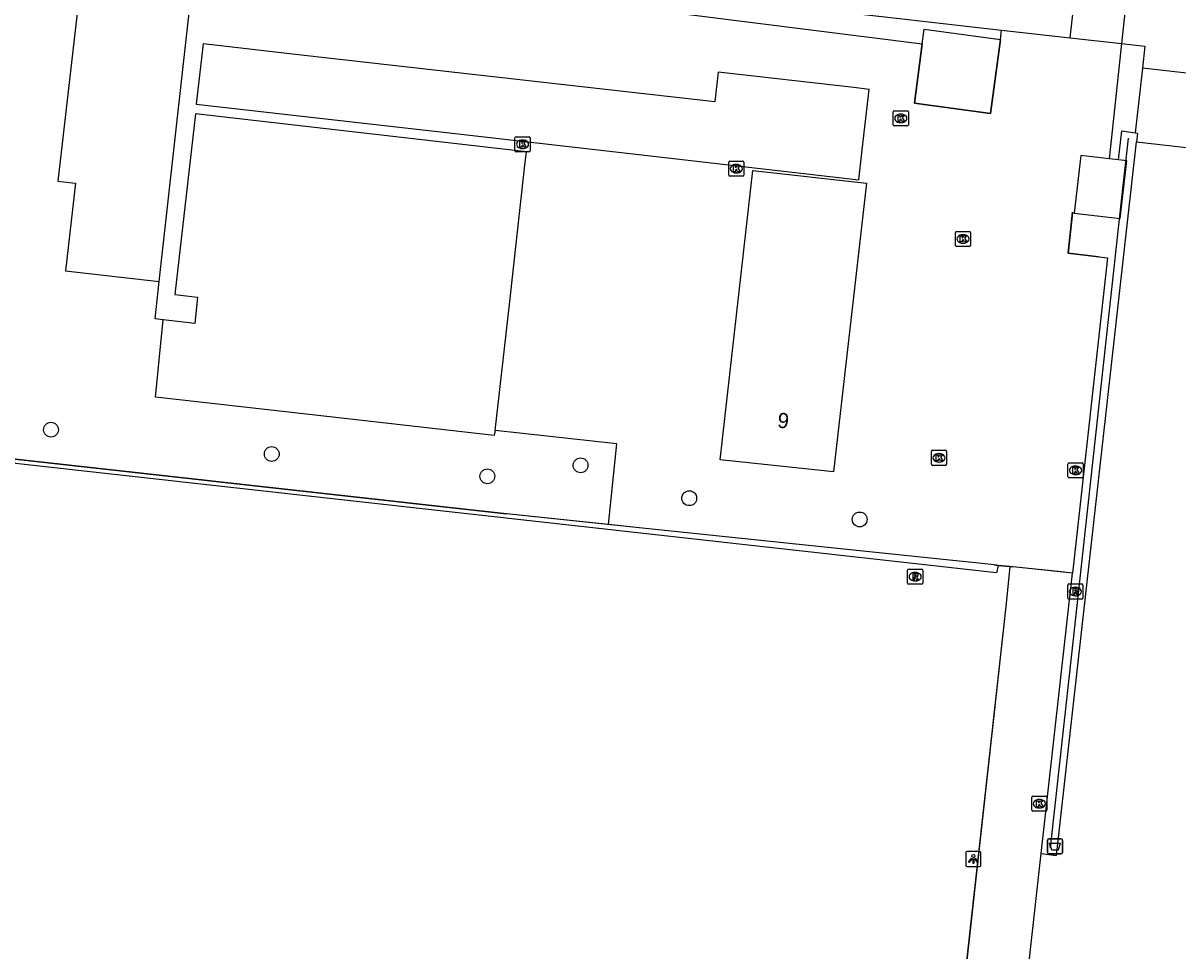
# Model space of a CAD drawing. Extents: x 162515 to 163909, y 388494 to 389773.
# Drawn here: x 162940.6 to 163016.8, y 388781.6 to 388842.8 of the extents above; entities that cross this region are included whole.
import ezdxf

# ---------------------------------------------------------------- set-up
doc = ezdxf.new("R2010")
doc.units = 0
for name, color, linetype in [('IMGEO_Afvalbak', 7, 'Continuous'), ('IMGEO_Boom', 7, 'Continuous'), ('IMGEO_Groenvoorziening', 7, 'Continuous'), ('IMGEO_Hek', 7, 'Continuous'), ('IMGEO_Houtwal', 7, 'Continuous'), ('IMGEO_Kolk', 7, 'Continuous'), ('IMGEO_Lichtpunt', 7, 'Continuous'), ('IMGEO_Loofbos', 7, 'Continuous'), ('IMGEO_Pand', 7, 'Continuous'), ('IMGEO_Pand_nummerreeks', 7, 'Continuous'), ('IMGEO_Rijbaan_lokaal_open', 7, 'Continuous'), ('IMGEO_Rioolput', 7, 'Continuous'), ('IMGEO_Voetpad_onverhard', 7, 'Continuous'), ('IMGEO_Voetpad_open', 7, 'Continuous')]:
    doc.layers.add(name, color=color, linetype=linetype)

msp = doc.modelspace()

# ---------------------------------------------------------------- linework, layer by layer
at = {"layer": 'IMGEO_Afvalbak'}
for p, q in [((163008.161, 388788.14), (163008.161, 388788.94)), ((163008.161, 388788.94), (163008.161, 388788.14)), ((163008.261, 388789.04), (163009.051, 388789.04)), ((163009.051, 388789.04), (163008.261, 388789.04)), ((163009.151, 388788.94), (163009.151, 388788.14)), ((163009.151, 388788.14), (163009.151, 388788.94)), ((163009.051, 388788.04), (163008.261, 388788.04)), ((163008.261, 388788.04), (163009.051, 388788.04))]:
    msp.add_line(p, q, dxfattribs=at)
msp.add_lwpolyline([(163008.304, 388788.754), (163009.008, 388788.754), (163008.859, 388788.284), (163008.453, 388788.284), (163008.304, 388788.754)], dxfattribs=at)
for centre, start, end in [((163008.261, 388788.94), 90, 180), ((163008.261, 388788.94), 90, 180), ((163009.051, 388788.94), 0, 90), ((163009.051, 388788.94), 360, 90), ((163008.261, 388788.14), 180, 270), ((163008.261, 388788.14), 180, 270), ((163009.051, 388788.14), 270, 0), ((163009.051, 388788.14), 270, 0)]:
    msp.add_arc(centre, 0.1, start, end, dxfattribs=at)
at = {"layer": 'IMGEO_Boom'}
for centre in [(162942.422, 388816.014), (162956.989, 388814.409), (162977.362, 388813.669), (162971.209, 388812.942), (162984.528, 388811.498), (162995.773, 388810.096)]:
    msp.add_circle(centre, 0.489, dxfattribs=at)
at = {"layer": 'IMGEO_Groenvoorziening'}
for points in [[(163004.9, 388807.069), (163004.798, 388806.577), (162867.846, 388821.822), (162872.238, 388860.105), (162871.559, 388861.161), (162799.041, 388869.269)], [(162979.197, 388809.763), (162972.476, 388810.468), (162868.327, 388822.062), (162872.602, 388861.371)], [(162999.905, 388841.465), (163000.034, 388842.427), (163005.06, 388841.755)]]:
    msp.add_lwpolyline(points, dxfattribs=at)
at = {"layer": 'IMGEO_Hek'}
for points in [[(162872.602, 388861.371), (162868.327, 388822.062), (162972.476, 388810.468)], [(162997.437, 388843.236), (163005.122, 388842.376), (163009.67, 388841.867)], [(162999.381, 388837.545), (162999.905, 388841.465), (163000.034, 388842.427)], [(163000.034, 388842.427), (163005.06, 388841.755)], [(163005.06, 388841.755), (163004.407, 388836.873)], [(163009.67, 388841.867), (163013.046, 388841.484)], [(163013.046, 388841.484), (163014.583, 388841.309), (163014.422, 388839.85)], [(163014.422, 388839.85), (163013.951, 388835.598)], [(163004.407, 388836.873), (162999.381, 388837.545)], [(163008.368, 388788.444), (163009.813, 388801.599), (163013.076, 388831.3), (163013.51, 388835.244)], [(163014.044, 388835.011), (163119.889, 388822.986), (163111.679, 388750)], [(163011.529, 388827.418), (163009.522, 388827.661), (163009.819, 388830.371)], [(162981.636, 388809.507), (162972.476, 388810.468)], [(163003.824, 388807.181), (163000, 388807.582), (162981.636, 388809.507)], [(163004.637, 388807.096), (163003.824, 388807.181)], [(163004.637, 388807.096), (163004.9, 388807.069)], [(163005.689, 388806.988), (163005.427, 388804.551), (162995.492, 388714.399)], [(163004.9, 388807.069), (163005.689, 388806.988), (163005.868, 388806.969)], [(163009.285, 388806.615), (163005.868, 388806.969)]]:
    msp.add_lwpolyline(points, dxfattribs=at)
at = {"layer": 'IMGEO_Houtwal'}
msp.add_lwpolyline([(162872.602, 388861.371), (162879.687, 388860.474), (162888.818, 388859.069), (162976.404, 388845.59), (162997.437, 388843.236), (163005.122, 388842.376)], dxfattribs=at)
at = {"layer": 'IMGEO_Kolk'}
for p, q in [((162997.987, 388836.122), (162997.987, 388836.974)), ((162998.062, 388837.048), (162998.914, 388837.048)), ((162998.475, 388836.828), (162998.5, 388836.828)), ((162998.988, 388836.974), (162998.988, 388836.122)), ((162998.914, 388836.048), (162998.062, 388836.048)), ((162998.498, 388836.268), (162998.473, 388836.268)), ((162973.109, 388835.341), (162973.961, 388835.341)), ((162973.034, 388834.415), (162973.034, 388835.267)), ((162973.545, 388834.561), (162973.52, 388834.561)), ((162973.522, 388835.121), (162973.547, 388835.121)), ((162974.035, 388835.267), (162974.035, 388834.415)), ((162973.961, 388834.341), (162973.109, 388834.341)), ((162987.135, 388832.805), (162987.135, 388833.657)), ((162987.21, 388833.731), (162988.062, 388833.731)), ((162987.623, 388833.511), (162987.648, 388833.511)), ((162988.136, 388833.657), (162988.136, 388832.805)), ((162988.062, 388832.731), (162987.21, 388832.731)), ((162987.646, 388832.951), (162987.621, 388832.951)), ((163002.092, 388828.171), (163002.092, 388829.023)), ((163002.167, 388829.097), (163003.019, 388829.097)), ((163002.58, 388828.877), (163002.605, 388828.877)), ((163003.093, 388829.023), (163003.093, 388828.171)), ((163003.019, 388828.097), (163002.167, 388828.097)), ((163002.603, 388828.317), (163002.578, 388828.317)), ((163000.505, 388813.732), (163000.505, 388814.584)), ((163000.58, 388814.658), (163001.432, 388814.658)), ((163000.993, 388814.438), (163001.018, 388814.438)), ((163001.506, 388814.584), (163001.506, 388813.732)), ((163001.432, 388813.658), (163000.58, 388813.658)), ((163001.016, 388813.878), (163000.991, 388813.878)), ((163009.516, 388812.91), (163009.516, 388813.762)), ((163009.591, 388813.836), (163010.443, 388813.836)), ((163010.004, 388813.616), (163010.029, 388813.616)), ((163010.517, 388813.762), (163010.517, 388812.91)), ((163010.443, 388812.836), (163009.591, 388812.836)), ((163010.027, 388813.056), (163010.002, 388813.056)), ((163007.128, 388790.922), (163007.128, 388791.774)), ((163007.203, 388791.848), (163008.055, 388791.848)), ((163007.616, 388791.628), (163007.641, 388791.628)), ((163008.129, 388791.774), (163008.129, 388790.922)), ((163008.055, 388790.848), (163007.203, 388790.848)), ((163007.639, 388791.068), (163007.614, 388791.068))]:
    msp.add_line(p, q, dxfattribs=at)
for points in [[(162997.987, 388836.122), (162997.987, 388836.974)], [(162998.062, 388837.048), (162998.914, 388837.048)], [(162998.988, 388836.974), (162998.988, 388836.122)], [(162998.914, 388836.048), (162998.062, 388836.048)], [(162998.308, 388836.748), (162998.431, 388836.748), (162998.431, 388836.597), (162998.561, 388836.748), (162998.725, 388836.748), (162998.579, 388836.597), (162998.732, 388836.348), (162998.58, 388836.348), (162998.495, 388836.512), (162998.431, 388836.445), (162998.431, 388836.348), (162998.308, 388836.348), (162998.308, 388836.748)], [(162973.109, 388835.341), (162973.961, 388835.341)], [(162973.034, 388834.415), (162973.034, 388835.267)], [(162973.355, 388835.041), (162973.478, 388835.041), (162973.478, 388834.89), (162973.608, 388835.041), (162973.772, 388835.041), (162973.626, 388834.89), (162973.779, 388834.641), (162973.627, 388834.641), (162973.542, 388834.805), (162973.478, 388834.738), (162973.478, 388834.641), (162973.355, 388834.641), (162973.355, 388835.041)], [(162974.035, 388835.267), (162974.035, 388834.415)], [(162973.961, 388834.341), (162973.109, 388834.341)], [(162987.135, 388832.805), (162987.135, 388833.657)], [(162987.21, 388833.731), (162988.062, 388833.731)], [(162987.456, 388833.431), (162987.579, 388833.431), (162987.579, 388833.28), (162987.709, 388833.431), (162987.873, 388833.431), (162987.727, 388833.28), (162987.88, 388833.031), (162987.728, 388833.031), (162987.643, 388833.195), (162987.579, 388833.128), (162987.579, 388833.031), (162987.456, 388833.031), (162987.456, 388833.431)], [(162988.136, 388833.657), (162988.136, 388832.805)], [(162988.062, 388832.731), (162987.21, 388832.731)], [(163002.092, 388828.171), (163002.092, 388829.023)], [(163002.167, 388829.097), (163003.019, 388829.097)], [(163002.413, 388828.797), (163002.536, 388828.797), (163002.536, 388828.646), (163002.666, 388828.797), (163002.83, 388828.797), (163002.684, 388828.646), (163002.837, 388828.397), (163002.685, 388828.397), (163002.6, 388828.561), (163002.536, 388828.494), (163002.536, 388828.397), (163002.413, 388828.397), (163002.413, 388828.797)], [(163003.093, 388829.023), (163003.093, 388828.171)], [(163003.019, 388828.097), (163002.167, 388828.097)], [(163000.505, 388813.732), (163000.505, 388814.584)], [(163000.58, 388814.658), (163001.432, 388814.658)], [(163000.826, 388814.358), (163000.949, 388814.358), (163000.949, 388814.207), (163001.079, 388814.358), (163001.243, 388814.358), (163001.097, 388814.207), (163001.25, 388813.958), (163001.098, 388813.958), (163001.013, 388814.122), (163000.949, 388814.055), (163000.949, 388813.958), (163000.826, 388813.958), (163000.826, 388814.358)], [(163001.506, 388814.584), (163001.506, 388813.732)], [(163001.432, 388813.658), (163000.58, 388813.658)], [(163009.516, 388812.91), (163009.516, 388813.762)], [(163009.591, 388813.836), (163010.443, 388813.836)], [(163009.837, 388813.536), (163009.96, 388813.536), (163009.96, 388813.385), (163010.09, 388813.536), (163010.254, 388813.536), (163010.108, 388813.385), (163010.261, 388813.136), (163010.109, 388813.136), (163010.024, 388813.3), (163009.96, 388813.233), (163009.96, 388813.136), (163009.837, 388813.136), (163009.837, 388813.536)], [(163010.517, 388813.762), (163010.517, 388812.91)], [(163010.443, 388812.836), (163009.591, 388812.836)], [(163007.128, 388790.922), (163007.128, 388791.774)], [(163007.203, 388791.848), (163008.055, 388791.848)], [(163007.449, 388791.548), (163007.572, 388791.548), (163007.572, 388791.397), (163007.702, 388791.548), (163007.866, 388791.548), (163007.72, 388791.397), (163007.873, 388791.148), (163007.721, 388791.148), (163007.636, 388791.312), (163007.572, 388791.245), (163007.572, 388791.148), (163007.449, 388791.148), (163007.449, 388791.548)], [(163008.129, 388791.774), (163008.129, 388790.922)], [(163008.055, 388790.848), (163007.203, 388790.848)]]:
    msp.add_lwpolyline(points, dxfattribs=at)
for centre, start, end in [((162998.064, 388836.972), 91.55205, 178.44795), ((162998.064, 388836.972), 91.55205, 178.44795), ((162998.912, 388836.972), 1.55205, 88.44795), ((162998.912, 388836.972), 1.55205, 88.44795), ((162998.064, 388836.124), 181.55205, 268.44795), ((162998.064, 388836.124), 181.55205, 268.44795), ((162998.912, 388836.124), 271.55205, 358.44795), ((162998.912, 388836.124), 271.55205, 358.44795), ((162973.111, 388835.265), 91.55205, 178.44795), ((162973.111, 388835.265), 91.55205, 178.44795), ((162973.959, 388835.265), 1.55205, 88.44795), ((162973.959, 388835.265), 1.55205, 88.44795), ((162973.111, 388834.417), 181.55205, 268.44795), ((162973.111, 388834.417), 181.55205, 268.44795), ((162973.959, 388834.417), 271.55205, 358.44795), ((162973.959, 388834.417), 271.55205, 358.44795), ((162987.212, 388833.655), 91.55205, 178.44795), ((162987.212, 388833.655), 91.55205, 178.44795), ((162988.06, 388833.655), 1.55205, 88.44795), ((162988.06, 388833.655), 1.55205, 88.44795), ((162987.212, 388832.807), 181.55205, 268.44795), ((162987.212, 388832.807), 181.55205, 268.44795), ((162988.06, 388832.807), 271.55205, 358.44795), ((162988.06, 388832.807), 271.55205, 358.44795), ((163002.169, 388829.021), 91.55205, 178.44795), ((163002.169, 388829.021), 91.55205, 178.44795), ((163003.017, 388829.021), 1.55205, 88.44795), ((163003.017, 388829.021), 1.55205, 88.44795), ((163002.169, 388828.173), 181.55205, 268.44795), ((163002.169, 388828.173), 181.55205, 268.44795), ((163003.017, 388828.173), 271.55205, 358.44795), ((163003.017, 388828.173), 271.55205, 358.44795), ((163000.582, 388814.582), 91.55205, 178.44795), ((163000.582, 388814.582), 91.55205, 178.44795), ((163001.43, 388814.582), 1.55205, 88.44795), ((163001.43, 388814.582), 1.55205, 88.44795), ((163000.582, 388813.734), 181.55205, 268.44795), ((163000.582, 388813.734), 181.55205, 268.44795), ((163001.43, 388813.734), 271.55205, 358.44795), ((163001.43, 388813.734), 271.55205, 358.44795), ((163009.593, 388813.76), 91.55205, 178.44795), ((163009.593, 388813.76), 91.55205, 178.44795), ((163010.441, 388813.76), 1.55205, 88.44795), ((163010.441, 388813.76), 1.55205, 88.44795), ((163009.593, 388812.912), 181.55205, 268.44795), ((163009.593, 388812.912), 181.55205, 268.44795), ((163010.441, 388812.912), 271.55205, 358.44795), ((163010.441, 388812.912), 271.55205, 358.44795), ((163007.205, 388791.772), 91.55205, 178.44795), ((163007.205, 388791.772), 91.55205, 178.44795), ((163008.053, 388791.772), 1.55205, 88.44795), ((163008.053, 388791.772), 1.55205, 88.44795), ((163007.205, 388790.924), 181.55205, 268.44795), ((163007.205, 388790.924), 181.55205, 268.44795), ((163008.053, 388790.924), 271.55205, 358.44795), ((163008.053, 388790.924), 271.55205, 358.44795)]:
    msp.add_arc(centre, 0.0765, start, end, dxfattribs=at)
for centre, major_axis, ratio, start_param, end_param in [((162998.474, 388836.548), (-0.387, 0.002), 0.722429, 4.712389, 7.853982), ((162998.499, 388836.548), (-0.39, 0.002), 0.717154, 1.570796, 4.712389), ((162973.521, 388834.841), (-0.387, 0.002), 0.722429, 4.712389, 7.853982), ((162973.546, 388834.841), (-0.39, 0.002), 0.717154, 1.570796, 4.712389), ((162987.622, 388833.231), (-0.387, 0.002), 0.722429, 4.712389, 7.853982), ((162987.647, 388833.231), (-0.39, 0.002), 0.717154, 1.570796, 4.712389), ((163002.579, 388828.597), (-0.387, 0.002), 0.722429, 4.712389, 7.853982), ((163002.604, 388828.597), (-0.39, 0.002), 0.717154, 1.570796, 4.712389), ((163000.992, 388814.158), (-0.387, 0.002), 0.722429, 4.712389, 7.853982), ((163001.017, 388814.158), (-0.39, 0.002), 0.717154, 1.570796, 4.712389), ((163010.003, 388813.336), (-0.387, 0.002), 0.722429, 4.712389, 7.853982), ((163010.028, 388813.336), (-0.39, 0.002), 0.717154, 1.570796, 4.712389), ((163007.615, 388791.348), (-0.387, 0.002), 0.722429, 4.712389, 7.853982), ((163007.64, 388791.348), (-0.39, 0.002), 0.717154, 1.570796, 4.712389)]:
    msp.add_ellipse(centre, major_axis=major_axis, ratio=ratio, start_param=start_param, end_param=end_param, dxfattribs=at)
at = {"layer": 'IMGEO_Lichtpunt'}
for p, q in [((163002.775, 388788.101), (163002.775, 388787.294)), ((163002.775, 388788.101), (163002.775, 388787.294)), ((163003.677, 388788.196), (163002.869, 388788.196)), ((163003.677, 388788.196), (163002.869, 388788.196)), ((163003.771, 388787.294), (163003.771, 388788.101)), ((163003.771, 388787.294), (163003.771, 388788.101)), ((163002.869, 388787.2), (163003.677, 388787.2)), ((163002.869, 388787.2), (163003.677, 388787.2))]:
    msp.add_line(p, q, dxfattribs=at)
for points in [[(163003.149, 388787.765), (163003.188, 388787.737), (163003, 388787.475), (163002.962, 388787.502), (163003.149, 388787.765)], [(163003.251, 388787.717), (163003.298, 388787.717), (163003.298, 388787.395), (163003.251, 388787.395), (163003.251, 388787.717)], [(163003.361, 388787.737), (163003.399, 388787.764), (163003.586, 388787.502), (163003.547, 388787.474), (163003.361, 388787.737)]]:
    msp.add_lwpolyline(points, dxfattribs=at)
msp.add_circle((163003.274, 388787.899), 0.0994, dxfattribs=at)
for centre, start, end in [((163002.869, 388788.101), 90, 180), ((163002.869, 388788.101), 90, 180), ((163003.677, 388788.101), 0, 90), ((163003.677, 388788.101), 0, 90), ((163002.869, 388787.294), 180, 270), ((163002.869, 388787.294), 180, 270), ((163003.677, 388787.294), 270, 0), ((163003.677, 388787.294), 270, 360)]:
    msp.add_arc(centre, 0.0946, start, end, dxfattribs=at)
at = {"layer": 'IMGEO_Loofbos'}
msp.add_lwpolyline([(163014.044, 388835.011), (163119.889, 388822.986), (163111.679, 388750), (163104.95, 388690.968)], dxfattribs=at)
at = {"layer": 'IMGEO_Pand'}
for points in [[(163012.226, 388833.889), (163010.366, 388834.104), (163009.927, 388830.299)], [(163009.927, 388830.299), (163012.968, 388829.949), (163013.407, 388833.753), (163012.85, 388833.817)], [(163012.85, 388833.817), (163012.226, 388833.889)], [(162988.731, 388833.119), (162996.215, 388832.282), (162994.057, 388813.226), (162986.579, 388814.028), (162988.731, 388833.119)]]:
    msp.add_lwpolyline(points, dxfattribs=at)
at = {"layer": 'IMGEO_Rijbaan_lokaal_open'}
for points in [[(163013.705, 388847.595), (163013.046, 388841.484)], [(163009.67, 388841.867), (163009.923, 388844.191)], [(163009.67, 388841.867), (163013.046, 388841.484)]]:
    msp.add_lwpolyline(points, dxfattribs=at)
at = {"layer": 'IMGEO_Rioolput'}
for p, q in [((162998.933, 388805.896), (162998.933, 388806.748)), ((162999.008, 388806.822), (162999.86, 388806.822)), ((162999.421, 388806.602), (162999.446, 388806.602)), ((162999.934, 388806.748), (162999.934, 388805.896)), ((162999.86, 388805.822), (162999.008, 388805.822)), ((162999.444, 388806.042), (162999.419, 388806.042)), ((163009.499, 388804.914), (163009.499, 388805.766)), ((163009.574, 388805.84), (163010.426, 388805.84)), ((163009.987, 388805.62), (163010.012, 388805.62)), ((163010.5, 388805.766), (163010.5, 388804.914)), ((163010.426, 388804.84), (163009.574, 388804.84)), ((163010.01, 388805.06), (163009.985, 388805.06))]:
    msp.add_line(p, q, dxfattribs=at)
for points in [[(162998.933, 388805.896), (162998.933, 388806.748)], [(162999.008, 388806.822), (162999.86, 388806.822)], [(162999.522, 388806.52), (162999.27, 388806.522), (162999.27, 388806.122)], [(162999.448, 388806.441), (162999.394, 388806.441), (162999.394, 388806.36)], [(162999.394, 388806.36), (162999.446, 388806.36)], [(162999.934, 388806.748), (162999.934, 388805.896)], [(162999.86, 388805.822), (162999.008, 388805.822)], [(162999.27, 388806.122), (162999.394, 388806.122), (162999.394, 388806.284), (162999.405, 388806.284)], [(162999.452, 388806.255), (162999.523, 388806.122), (162999.663, 388806.122), (162999.598, 388806.248)], [(163009.499, 388804.914), (163009.499, 388805.766)], [(163009.574, 388805.84), (163010.426, 388805.84)], [(163010.5, 388805.766), (163010.5, 388804.914)], [(163010.426, 388804.84), (163009.574, 388804.84)], [(163010.088, 388805.538), (163009.836, 388805.54), (163009.836, 388805.14)], [(163009.836, 388805.14), (163009.96, 388805.14), (163009.96, 388805.302), (163009.971, 388805.302)], [(163010.014, 388805.459), (163009.96, 388805.459), (163009.96, 388805.378)], [(163009.96, 388805.378), (163010.012, 388805.378)], [(163010.018, 388805.273), (163010.089, 388805.14), (163010.229, 388805.14), (163010.164, 388805.266)]]:
    msp.add_lwpolyline(points, dxfattribs=at)
for centre, radius, start, end in [((162999.01, 388806.746), 0.0765, 91.55205, 178.44795), ((162999.01, 388806.746), 0.0765, 91.55205, 178.44795), ((162999.43, 388806.549), 0.19, 274.7715, 282.96867), ((162999.454, 388806.345), 0.0964, 77.00612, 93.18647), ((162999.468, 388806.402), 0.0378, 276.66336, 79.67722), ((162999.521, 388806.41), 0.109, 350.36119, 89.41601), ((162999.519, 388806.41), 0.112, 277.58423, 350.98172), ((162999.858, 388806.746), 0.0765, 1.55205, 88.44795), ((162999.858, 388806.746), 0.0765, 1.55205, 88.44795), ((162999.01, 388805.898), 0.0765, 181.55205, 268.44795), ((162999.01, 388805.898), 0.0765, 181.55205, 268.44795), ((162999.404, 388806.231), 0.0533, 26.02933, 88.69889), ((162999.503, 388806.195), 0.108, 29.51342, 73.79051), ((162999.858, 388805.898), 0.0765, 271.55205, 358.44795), ((162999.858, 388805.898), 0.0765, 271.55205, 358.44795), ((163009.576, 388805.764), 0.0765, 91.55205, 178.44795), ((163009.576, 388805.764), 0.0765, 91.55205, 178.44795), ((163010.424, 388805.764), 0.0765, 1.55205, 88.44795), ((163010.424, 388805.764), 0.0765, 1.55205, 88.44795), ((163009.576, 388804.916), 0.0765, 181.55205, 268.44795), ((163009.576, 388804.916), 0.0765, 181.55205, 268.44795), ((163009.97, 388805.249), 0.0533, 26.02933, 88.69889), ((163009.996, 388805.567), 0.19, 274.7715, 282.96867), ((163010.02, 388805.363), 0.0964, 77.00612, 93.18647), ((163010.034, 388805.42), 0.0378, 276.66336, 79.67722), ((163010.087, 388805.428), 0.109, 350.36119, 89.41601), ((163010.085, 388805.428), 0.112, 277.58423, 350.98172), ((163010.069, 388805.213), 0.108, 29.51342, 73.79051), ((163010.424, 388804.916), 0.0765, 271.55205, 358.44795), ((163010.424, 388804.916), 0.0765, 271.55205, 358.44795)]:
    msp.add_arc(centre, radius, start, end, dxfattribs=at)
for centre, major_axis, ratio, start_param, end_param in [((162999.42, 388806.322), (-0.387, 0.002), 0.722429, 4.712389, 7.853982), ((162999.445, 388806.322), (-0.39, 0.002), 0.717154, 1.570796, 4.712389), ((163009.986, 388805.34), (-0.387, 0.002), 0.722429, 4.712389, 7.853982), ((163010.011, 388805.34), (-0.39, 0.002), 0.717154, 1.570796, 4.712389)]:
    msp.add_ellipse(centre, major_axis=major_axis, ratio=ratio, start_param=start_param, end_param=end_param, dxfattribs=at)
at = {"layer": 'IMGEO_Voetpad_onverhard'}
msp.add_lwpolyline([(163126.231, 388787.847), (163125.858, 388790.634), (163123.55, 388799.176), (163125.824, 388819.514), (163124.377, 388827.421), (163014.422, 388839.85)], dxfattribs=at)
at = {"layer": 'IMGEO_Voetpad_open'}
for points in [[(162951.853, 388846.32), (162951.985, 388847.505), (162999.905, 388841.465)], [(162951.853, 388846.32), (162944.568, 388847.133), (162942.876, 388832.417), (162944.053, 388832.282), (162943.388, 388826.504), (162949.563, 388825.794)], [(162949.563, 388825.794), (162951.652, 388844.52), (162951.853, 388846.32)], [(163005.06, 388841.755), (163005.122, 388842.376)], [(163005.122, 388842.376), (163009.67, 388841.867)], [(162995.94, 388834.483), (162996.391, 388838.463), (162995.379, 388838.578), (162986.443, 388839.59), (162986.214, 388837.63), (162959.136, 388840.698), (162952.454, 388841.455), (162952.006, 388837.489), (162969.276, 388835.519), (162981.195, 388834.159), (162995.716, 388832.502), (162995.94, 388834.483)], [(162999.905, 388841.465), (162999.381, 388837.545), (163004.407, 388836.873), (163005.06, 388841.755)], [(163013.046, 388841.484), (163012.38, 388835.312), (163012.226, 388833.889)], [(163013.046, 388841.484), (163014.583, 388841.309), (163014.422, 388839.85)], [(163014.422, 388839.85), (163013.951, 388835.598)], [(162971.737, 388815.952), (162972.667, 388824.272), (162973.673, 388833.273), (162973.793, 388834.351), (162970.92, 388834.679), (162951.965, 388836.845), (162950.596, 388824.938), (162952.094, 388824.764), (162951.905, 388823.012), (162949.815, 388823.253)], [(163012.85, 388833.817), (163013.063, 388835.727), (163013.951, 388835.598)], [(163013.951, 388835.598), (163014.107, 388835.576), (163014.044, 388835.011)], [(163007.737, 388788.054), (163008.756, 388787.944), (163014.044, 388835.011)], [(163009.927, 388830.299), (163009.813, 388830.312), (163009.522, 388827.661), (163012.127, 388827.346), (163009.805, 388806.561)], [(162949.815, 388823.253), (162949.289, 388823.333), (162949.563, 388825.794)], [(162971.737, 388815.952), (162971.669, 388815.631), (162960.815, 388816.865), (162949.322, 388818.171), (162949.815, 388823.253)], [(162979.197, 388809.763), (162979.755, 388815.086), (162971.737, 388815.952)], [(163004.9, 388807.069), (163004.637, 388807.096), (163003.824, 388807.181), (163000, 388807.582), (162981.636, 388809.507), (162979.197, 388809.763)], [(163005.689, 388806.988), (163005.427, 388804.551), (163000, 388755.61), (162999.38, 388750), (162995.492, 388714.399), (162994.789, 388707.964), (162994.733, 388707.565), (162994.603, 388706.959), (162994.418, 388706.366), (162994.182, 388705.792), (162993.895, 388705.241), (162993.56, 388704.718), (162993.179, 388704.228), (162992.757, 388703.773), (162992.295, 388703.358), (162991.798, 388702.985), (162991.27, 388702.659), (162990.715, 388702.381), (162990.137, 388702.154), (162989.541, 388701.979), (162988.932, 388701.858), (162988.315, 388701.792)], [(163005.689, 388806.988), (163004.9, 388807.069)], [(163009.805, 388806.561), (163005.868, 388806.969), (163005.689, 388806.988)], [(163007.737, 388788.054), (163009.805, 388806.561)], [(163003.56, 388750.47), (163007.737, 388788.054)]]:
    msp.add_lwpolyline(points, dxfattribs=at)

# ---------------------------------------------------------------- texts
at = {"layer": 'IMGEO_Pand_nummerreeks'}
msp.add_text('9', height=1, rotation=353.87854, dxfattribs=at).set_placement((162990.312, 388816.162))

doc.saveas('drawing.dxf')
